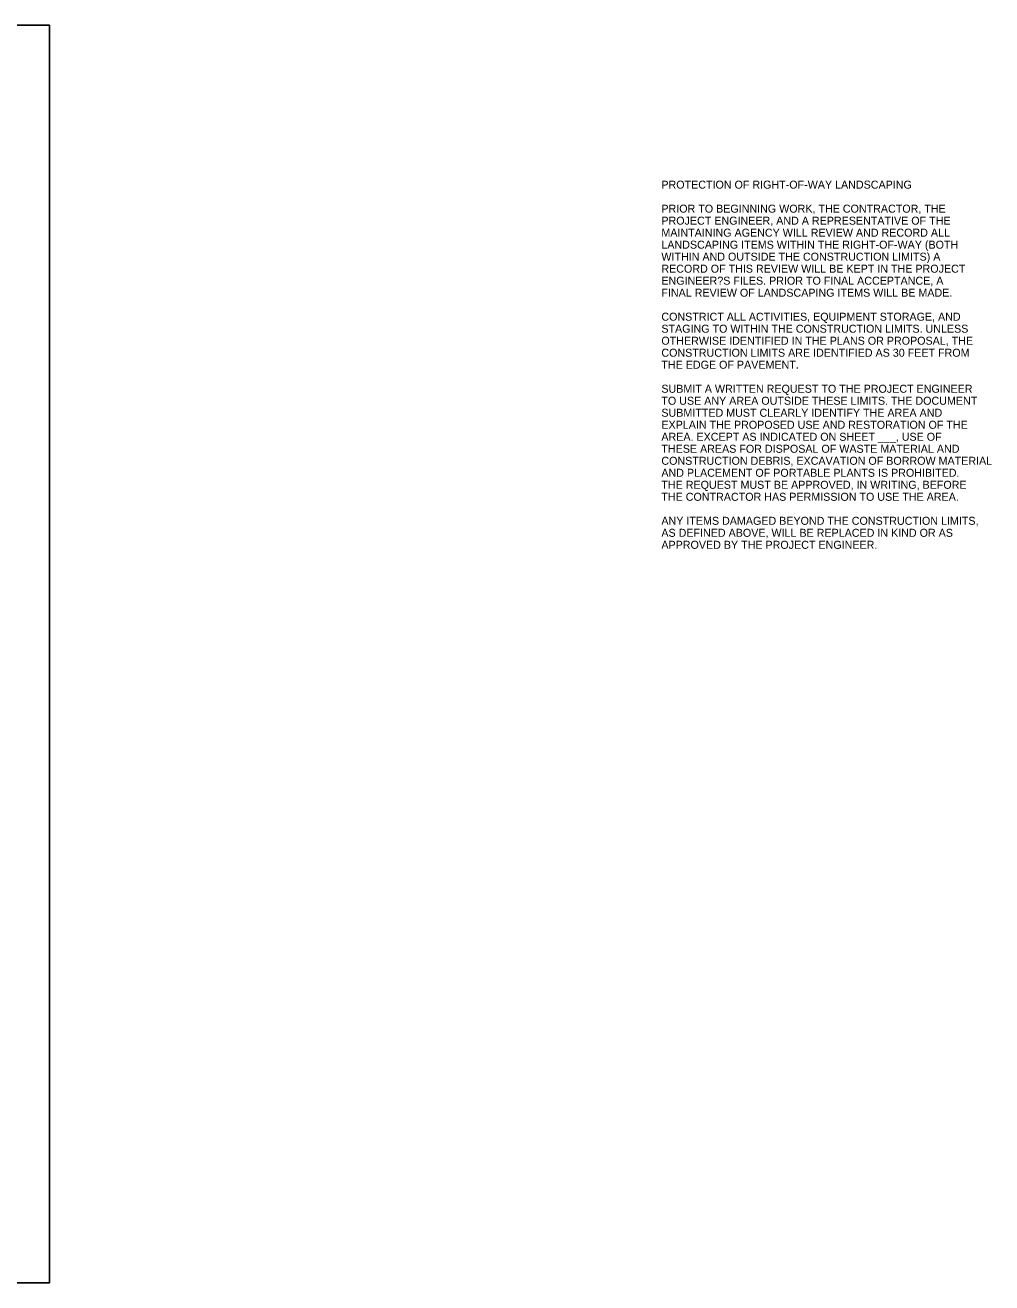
# Model space of a CAD drawing. Extents: x 0 to 50.5, y 0 to 22.
# Drawn here: x 33.58 to 50.48, y 0 to 22 of the extents above; entities that cross this region are included whole.
import ezdxf

# ---------------------------------------------------------------- set-up
doc = ezdxf.new("R2010")
doc.units = 0
doc.layers.add('SH_Cut_Line', color=7, linetype='Continuous')
doc.layers.add('SH_Text', color=7, linetype='Continuous')

msp = doc.modelspace()

# ---------------------------------------------------------------- linework, layer by layer
at = {"layer": 'SH_Cut_Line'}
msp.add_lwpolyline([(0, 0), (34, 0), (34, 22), (0, 22)], close=True, dxfattribs=at)

# ---------------------------------------------------------------- texts
at = {"layer": 'SH_Text'}
for s, p in [('PROTECTION OF RIGHT-OF-WAY LANDSCAPING', (44.698, 19.14)), ('PRIOR TO BEGINNING WORK, THE CONTRACTOR, THE', (44.698, 18.72)), ('PROJECT ENGINEER, AND A REPRESENTATIVE OF THE', (44.698, 18.51)), ('MAINTAINING AGENCY WILL REVIEW AND RECORD ALL', (44.698, 18.3)), ('LANDSCAPING ITEMS WITHIN THE RIGHT-OF-WAY (BOTH', (44.698, 18.09)), ('WITHIN AND OUTSIDE THE CONSTRUCTION LIMITS) A', (44.698, 17.88)), ('RECORD OF THIS REVIEW WILL BE KEPT IN THE PROJECT', (44.698, 17.67)), ('ENGINEER?S FILES. PRIOR TO FINAL ACCEPTANCE, A', (44.698, 17.46)), ('FINAL REVIEW OF LANDSCAPING ITEMS WILL BE MADE.', (44.698, 17.25)), ('CONSTRICT ALL ACTIVITIES, EQUIPMENT STORAGE, AND', (44.698, 16.83)), ('STAGING TO WITHIN THE CONSTRUCTION LIMITS. UNLESS', (44.698, 16.62)), ('OTHERWISE IDENTIFIED IN THE PLANS OR PROPOSAL, THE', (44.698, 16.41)), ('CONSTRUCTION LIMITS ARE IDENTIFIED AS 30 FEET FROM', (44.698, 16.2)), ('THE EDGE OF PAVEMENT.', (44.698, 15.99)), ('SUBMIT A WRITTEN REQUEST TO THE PROJECT ENGINEER', (44.698, 15.57)), ('TO USE ANY AREA OUTSIDE THESE LIMITS. THE DOCUMENT', (44.698, 15.36)), ('SUBMITTED MUST CLEARLY IDENTIFY THE AREA AND', (44.698, 15.15)), ('EXPLAIN THE PROPOSED USE AND RESTORATION OF THE', (44.698, 14.94)), ('AREA. EXCEPT AS INDICATED ON SHEET ___, USE OF', (44.698, 14.73)), ('THESE AREAS FOR DISPOSAL OF WASTE MATERIAL AND', (44.698, 14.52)), ('CONSTRUCTION DEBRIS, EXCAVATION OF BORROW MATERIAL', (44.698, 14.31)), ('AND PLACEMENT OF PORTABLE PLANTS IS PROHIBITED.', (44.698, 14.1)), ('THE REQUEST MUST BE APPROVED, IN WRITING, BEFORE', (44.698, 13.89)), ('THE CONTRACTOR HAS PERMISSION TO USE THE AREA.', (44.698, 13.68)), ('ANY ITEMS DAMAGED BEYOND THE CONSTRUCTION LIMITS,', (44.698, 13.26)), ('AS DEFINED ABOVE, WILL BE REPLACED IN KIND OR AS', (44.698, 13.05)), ('APPROVED BY THE PROJECT ENGINEER.', (44.698, 12.84))]:
    msp.add_text(s, height=0.14, dxfattribs=at).set_placement(p)

doc.saveas('drawing.dxf')
